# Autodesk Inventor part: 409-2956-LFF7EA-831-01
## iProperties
Created: 2010-09
Part Number: 409-2956-LFF7EA-831-01
Material: 3/8" OD TUBE - SS
Document SubType Name: Modeling
Designer: S. Boerckel
Engineer: Steve Boerckel
Mass: 61.6007 g
Surface Area: 127.01 cm^2
Volume: 7.62385 cm^3
Density: 8.08 g/cm^3
Description: LOWE PRESSURE GAUGE TUBE
Length: 13.302 in
Author: S. Boerckel
Revision Number: 0
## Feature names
1. Sweep3
